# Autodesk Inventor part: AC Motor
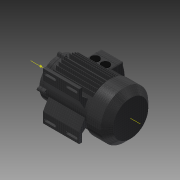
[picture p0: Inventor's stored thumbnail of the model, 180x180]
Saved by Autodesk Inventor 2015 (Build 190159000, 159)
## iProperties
Part Number: AC Motor
Document SubType Name: Modeling
Created: 2003-05
Description: ac-motor.ipt.
Density: 1 g/cm^3
Mass: 2583.35 g
Surface Area: 6107.9 cm^2
Volume: 2583.35 cm^3
Material: Generic
Appearance: Skid Plate
+MSCProtocol1+ProtocolID: P00030526084445659
+MSCProtocol2+Protocol: P00030526084445659<@PID>[Version]<@EL>Version=2.2<@EL>[Baseview]<@EL>InOpt=0<@EL>H2=574<@EL>W2=514<@EL>Top=160<@EL>Left=357<@EL>OnTop=0<@EL>UpdateAll=0<@EL>Enab
Control State: 0
Master: False
Checked Out: False
Shininess: 64.0
Length Units: 11272
Angle Units: 11279
Time Units: 11290
Mass Units: 11286
Length Display Precision: 3
Angle Display Precision: 2
Compacted: True
Density: 0.0
Volumn: 0.0
Area: 0.0
PropertySet Name: Model Information
Author: Autodesk, Inc.
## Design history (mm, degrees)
sketch "Sketch1"
  geometry: L1 (0, 0)-(0, 45); L2 (6, 78)-(220, 78); L3 (220, 78)-(220, 98); L4 (220, 98)-(279.5, 98); L5 (279.5, 98)-(305, 72.5); L6 (305, 72.5)-(305, 0); L7 (305, 0)-(0, 0); L8 (0, 45)-(5, 45); L9 (5, 45)-(5, 60); L10 (5, 60)-(6, 60); L11 (6, 60)-(6, 78); L12 (220, 19)-(-5, 19); L13 (-5, 19)-(-5, 14); L14 (-5, 14)-(-65, 14); L15 (-65, 14)-(-65, 0); L16 (220, 19)-(220, 14); L17 (220, 14)-(279.5, 14); L18 (279.5, 14)-(279.5, 0); L19 (-65, 0)-(305, 0); L20 (305, 0)-(0, 0); L21 (0, 20)-(15, 20); L22 (15, 20)-(15, 68); L23 (15, 68)-(223, 68); L24 (223, 68)-(223, 95); L25 (223, 95)-(278.257, 95); L26 (278.257, 95)-(302, 71.257); L27 (302, 71.257)-(302, 0); L28 (-65, 0)-(279.5, 0); 3 further points
  constraints: 56 end point, 13 parallel, 10 perpendicular, 10 point on line, 3 collinear, 1 vertical, 1 other
  dimensions: "d0" = 196 diameter of L4 L7; "d4" = 63 distance from line of point (63, 0) L1; "d5" = 28 diameter of L14 L7; "d6" = 45 deg angle of L4 L5; "d8" = 60 distance of L13.end L14.end; "d9" = 1 distance between parallel lines of L11 L9; "d10" = 5 distance between parallel lines of L1 L9; "d12" = 5 distance between parallel lines of L13 L1; "d13" = 5 distance between parallel lines of L12 L14; "d17" = 25.5 horizontal distance of L4.end L5.end (derived); "d18" = 3 distance between parallel lines of L6 L27; "d19" = 3 distance between parallel lines of L5 L26; "d20" = 3 distance between parallel lines of L25 L4; "d21" = 3 distance between parallel lines of L3 L24; "d22" = 10 distance between parallel lines of L2 L23; "d23" = 15 distance between parallel lines of L1 L22; "d25" = 1 distance between parallel lines of L12 L21; "d79" = 78 distance between parallel lines of L2 L28 (= d67); "d180" = 25 distance between parallel lines of L8 L21; "d181" = 40 distance between parallel lines of L21 L10; "Size" = 310 distance between parallel lines of L13 L6; "d183" = 85 distance between parallel lines of L6 L3; "d184" = 44 distance from line of L1 point (44, 0); "d185" = 27 distance from line of point (193, 0) L3
revolve "Revolution1" stored, may be unused: angle "d24" = 90 deg
workplane "Work Plane8"
sketch "Sketch3"
  geometry: L1 (-100, 56)-(-100, 98); L2 (-100, 98)-(-88, 98); L3 (-88, 98)-(-88, 66); L4 (-88, 66)-(-63.435, 45.387); L5 (-100, 56)-(-76.489, 15.278); L6 (-76.489, -15.278)-(-100, -56); L7 (-100, -56)-(-100, -98); L8 (-100, -98)-(-88, -98); L9 (-88, -98)-(-88, -66); L10 (-88, -66)-(-63.435, -45.387); A1 r 78 centre (0, 0) between (-63.435, -45.387) and (-63.435, 45.387) reference; 3 further points
  constraints: 20 end point, 4 point on circle, 4 vertical alignment, 3 equal length, 3 parallel, 2 perpendicular, 2 point on line, 1 vertical
  dimensions: "d28" = 42 distance of L1.start L1.end; "d29" = 12 distance of L1.end L2.end; "d30" = 196 distance between parallel lines of L8 L2; "d31" = 20 deg angle of L10 L6; "d33" = 30 deg angle of L6 L7; "d38" = 160 distance of point (-100, -80) point (-100, 80); "d39" = 18 distance from line of L8 point (-100, -80) (= -0.5 x d38 + 0.5 x d30); "d53" = 10 vertical distance of L1.start L3.end (computed from d29); "d54" = 100 distance from line of point (0, 0) L7
extrude "Extrusion1" join sketch "Sketch3" stored distance "d35" = 176 (= d2); taper "d36" = 0 deg
workplane "Work Plane1"
sketch "Sketch2"
  geometry: L1 (49.84, 60)-(128, 60); L2 (128, 60)-(128, 45); L3 (49.84, -60)-(128, -60); L4 (128, -60)-(128, -45); L5 (-120.6, 0)-(177.6, 0) reference; A1 r 148.143 centre (-13.143, 0) between (128, -45) and (128, 45); A2 r 78 centre (0, 0) between (49.84, 60) and (49.84, -60) reference
  constraints: 8 end point, 4 point on circle, 3 perpendicular, 2 point on line, 1 centre point, 1 horizontal, 1 vertical alignment
  dimensions: "d57" = 7 distance edge to line of A1 L2; "d58" = 15 distance of L1.end L2.end; "d60" = 120 distance between parallel lines of L3 L1; "d186" = 128 distance from line of A2.centre L4
extrude "Extrusion2" join sketch "Sketch2" stored distance "d62" = 92 (computed from d27); taper "d63" = 0 deg
sketch "Sketch5"
  geometry: L1 (0, 0)-(92, 0) reference; L2 (0, 0)-(0, -78.16) reference; L3 (-117, -128)-(310, -128) reference; L4 (46, 54)-(46, -275) reference; L5 (67, -50)-(25, -50); C1 r 16.25 at (25, -50); C2 r 16.25 at (67, -50); 2 further points
  constraints: 2 centre point, 2 end point, 2 point on line, 1 equal radius, 1 horizontal alignment, 1 midpoint, 1 parallel, 1 perpendicular
  dimensions: "d61" = 32.5 diameter of C1; "d66" = 42 distance of L5.start L5.end; "d67" = 78 distance from line of L3 L5.end; "d68" = 25 distance from line of L1 point (0, -25)
extrude "Extrusion3" join sketch "Sketch5" distance "d69" = 3; taper "d70" = 0 deg
workplane "Work Plane3"
sketch "Sketch7"
  geometry: L1 (92, 0)-(92, 120) reference; L2 (0, 120)-(0, 0) reference; L3 (0, 120)-(92, 120) reference; L4 (0, 0)-(92, 0) reference; L5 (1, 1)-(1, 119); L6 (1, 119)-(91, 119); L7 (91, 119)-(91, 1); L8 (91, 1)-(1, 1)
  constraints: 8 end point, 3 other
  dimensions: "d75" = 1 distance between parallel lines of L1 L7
extrude "Extrusion4" cut sketch "Sketch7" stored distance "d76" = 1; taper "d77" = 0 deg
workplane "Work Plane4"
sketch "Sketch8"
  geometry: C1 r 78 at (0, 0) reference; C2 r 77 at (0, 0)
  constraints: 1 centre point
  dimensions: "d81" = 1 radial gap between concentric circles of C1 C2
extrude "Extrusion5" cut sketch "Sketch8" stored distance "d82" = 1; taper "d83" = 0 deg
sketch "Sketch10"
  geometry: L1 (-5.796, 85.553)-(-7.928, 77.596); L2 (5.796, 85.553)-(7.928, 77.596); C1 r 77 at (0, 0) reference; A1 r 78 centre (0, 0) between (-7.928, 77.596) and (7.928, 77.596) reference; A2 r 6 centre (0, 84) between (5.796, 85.553) and (-5.796, 85.553); 1 further point
  constraints: 7 point on circle, 4 end point, 2 point on line, 2 tangent, 2 vertical alignment, 1 centre point, 1 horizontal alignment
  dimensions: "d89" = 6 radius of A2; "d90" = 6 distance of point (0, 78) A2.centre; "d91" = 30 deg angle of L2 L1
extrude "Extrusion7" join sketch "Sketch10" distance "d92" = 15; taper "d93" = 0 deg
sketch "Sketch11"
  geometry: L1 (5.796, 85.553)-(7.928, 77.596) reference; L2 (-7.928, 77.596)-(-5.796, 85.553) reference; A1 r 78 centre (0, 0) between (7.928, 77.596) and (-7.928, 77.596) reference; A2 r 6 centre (0, 84) between (5.796, 85.553) and (-5.796, 85.553) reference
extrude "Extrusion8" join sketch "Sketch11" distance "d94" = 13 (computed from d80); taper "d95" = 0 deg
sketch "Sketch12"
  geometry: A1 r 6 centre (0, 84) between (5.796, 85.553) and (-5.796, 85.553) reference
hole "Hole2" sketch "Sketch12" at (0, 84) diameter "d96" = 6; stored, may be unused: countersink angle "d100" = 82 deg, drill point angle "d102" = 118 deg; dims "d97" = 6, "d98" = 4, "d99" = 2, "d101" = 8
pattern_circular "Circular Pattern1" dims "d105" = 360 deg
fillet "Fillet1" dims "d106" = 2, "d188" = -10 (derived)
workplane "Work Plane5"
workplane "Work Plane6"
sketch "Sketch13"
  geometry: L1 (77.356, 10)-(95.071, 10); L2 (95.071, 10)-(95.071, 12); L3 (95.071, 12)-(77.071, 12); L4 (75.078, 21.15)-(92.793, 21.15); L5 (92.793, 21.15)-(92.793, 23.15); L6 (92.793, 23.15)-(74.485, 23.15); L7 (70.998, 32.3)-(88.713, 32.3); L8 (88.713, 32.3)-(88.713, 34.3); L9 (88.713, 34.3)-(70.054, 34.3); L10 (64.777, 43.45)-(82.492, 43.45); L11 (82.492, 43.45)-(82.492, 45.45); L12 (82.492, 45.45)-(63.39, 45.45); L13 (77.356, -10)-(95.071, -10); L14 (95.071, -10)-(95.071, -12); L15 (95.071, -12)-(77.071, -12); L16 (75.078, -21.15)-(92.485, -21.15); L17 (92.485, -21.15)-(92.485, -23.15); L18 (92.485, -23.15)-(74.485, -23.15); L19 (70.998, -32.3)-(88.054, -32.3); L20 (88.054, -32.3)-(88.054, -34.3); L21 (88.054, -34.3)-(70.054, -34.3); L22 (64.777, -43.45)-(81.39, -43.45); L23 (81.39, -43.45)-(81.39, -45.45); L24 (81.39, -45.45)-(63.39, -45.45); L25 (55.703, -54.6)-(71.67, -54.6); L26 (71.67, -54.6)-(71.67, -56.6); L27 (71.67, -56.6)-(53.67, -56.6); 1 further point
  constraints: 54 end point, 16 parallel, 11 equal length, 10 perpendicular, 1 horizontal, 1 vertical alignment, 19 other
  dimensions: "d110" = 2 distance of L1.end L2.end; "d112" = 10 distance from line of L1 point (0, 0); "d118" = 10 distance from line of L13 point (0, 0); "d122" = 18 distance of L17.end L18.end (= d123); "d123" = 18 distance of L14.end L15.end (computed from d67, d0); "d124" = 18 distance of L20.end L21.end (= d123); "d125" = 18 distance of L23.end L24.end (= d123); "d131" = 18 distance of L26.end L27.end (= d123); "d149" = 11.15 distance between parallel lines of L4 L1 (computed from d67); "d150" = 11.15 distance between parallel lines of L7 L4 (= d149); "d151" = 11.15 distance between parallel lines of L10 L7 (= d149); "d152" = 11.15 distance between parallel lines of L16 L13 (= d149); "d153" = 11.15 distance between parallel lines of L19 L16 (= d149); "d154" = 11.15 distance between parallel lines of L22 L19 (= d149); "d155" = 11.15 distance between parallel lines of L25 L22 (= d149)
extrude "Extrusion9" join sketch "Sketch13" stored distance "d108" = 10; taper "d109" = 0 deg
workplane "Work Plane7"
sketch "Sketch14"
  geometry: L1 (7, 77.685)-(7, 95.685); L2 (7, 95.685)-(9, 95.685); L3 (9, 95.685)-(9, 77.479); L4 (18.15, 75.859)-(18.15, 93.559); L5 (18.15, 93.559)-(20.15, 93.559); L6 (20.15, 93.559)-(20.15, 75.352); L7 (29.3, 72.288)-(29.3, 89.651); L8 (29.3, 89.651)-(31.3, 89.651); L9 (31.3, 89.651)-(31.3, 71.444); L10 (40.45, 66.692)-(40.45, 84.692); L11 (40.45, 84.692)-(42.45, 84.692); L12 (42.45, 84.692)-(42.45, 65.437); L13 (51.6, 58.493)-(51.6, 74.872); L14 (51.6, 74.872)-(53.6, 74.872); L15 (53.6, 74.872)-(53.6, 56.666); 1 further point
  constraints: 30 end point, 15 parallel, 6 perpendicular, 1 vertical, 11 other
  dimensions: "d132" = 7 distance from line of point (0, 0) L1; "d134" = 2 distance between parallel lines of L3 L1; "d138" = 18 distance of L1.start L1.end (= d123); "d156" = 11.15 distance between parallel lines of L4 L1 (= d149); "d157" = 11.15 distance between parallel lines of L7 L4 (= d149); "d158" = 11.15 distance between parallel lines of L10 L7 (= d149); "d159" = 11.15 distance between parallel lines of L13 L10 (= d149); "d178" = 18 distance of L10.start L10.end (= d123)
extrude "Extrusion10" join sketch "Sketch14" stored distance "d140" = 10; taper "d141" = 0 deg
sketch "Sketch15"
  geometry: L1 (53.6, 56.666)-(63.39, 45.45); L2 (58.101, 52.041)-(71.662, 63.878); L3 (71.662, 63.878)-(72.977, 62.371); L4 (72.977, 62.371)-(59.416, 50.535); L5 (58.495, 51.058)-(72.319, 63.125); A1 r 78 centre (0, 0) between (53.6, 56.666) and (63.39, 45.45) reference
  constraints: 10 end point, 2 midpoint, 2 parallel, 2 point on circle, 1 perpendicular, 1 point on line
  dimensions: "d146" = 2 distance of L2.end L3.end; "d160" = 18 distance of L3.end L4.end (= d123)
extrude "Extrusion11" join sketch "Sketch15" stored distance "d147" = 10; taper "d148" = 0 deg
mirror "Mirror4"
fillet "Fillet2" dims "d142" = 5, "d189" = -10 (derived)
fillet "Fillet3" dims "d143" = 4, "d190" = -10 (derived)
fillet "Fillet4" dims "d144" = 2, "d145" = 4, "d191" = -10 (derived)
workpoint "Work Point1"
sketch "Sketch19"
  geometry: L1 (0, 0)-(149, 0) reference; L2 (10.254, 11.113)-(48.354, 11.113); L3 (48.354, 11.113)-(48.354, 20.638); L4 (48.354, 20.638)-(10.254, 20.637); L5 (10.254, 20.637)-(10.254, 11.113); 2 further points
  constraints: 8 end point, 2 midpoint, 2 parallel, 2 vertical alignment, 1 horizontal, 1 perpendicular, 4 other
  dimensions: "d194" = 15.875 distance from line of L1 point (10.254, 15.875); "d195" = 9.525 distance between parallel lines of L4 L2; "d196" = 38.1 distance between parallel lines of L3 L5
extrude "Extrusion13" cut sketch "Sketch19" stored distance "d197" = 10; taper "d198" = 0 deg
pattern_linear "Rectangular Pattern2" dims "d201" = 88.9, "d204" = 165.1
workaxis "Work Axis2"
body "Solid1"
workplane "Work Plane"
other parameters: "d2" = 176, "d3" = 23 (= -0.5 x d1 + 0.5 x d37), "d7" = 372, "d27" = 102, "d37" = 186 (computed from d2), "d80" = -16, "d107" = 5, "d117" = 5, "d139" = 5
